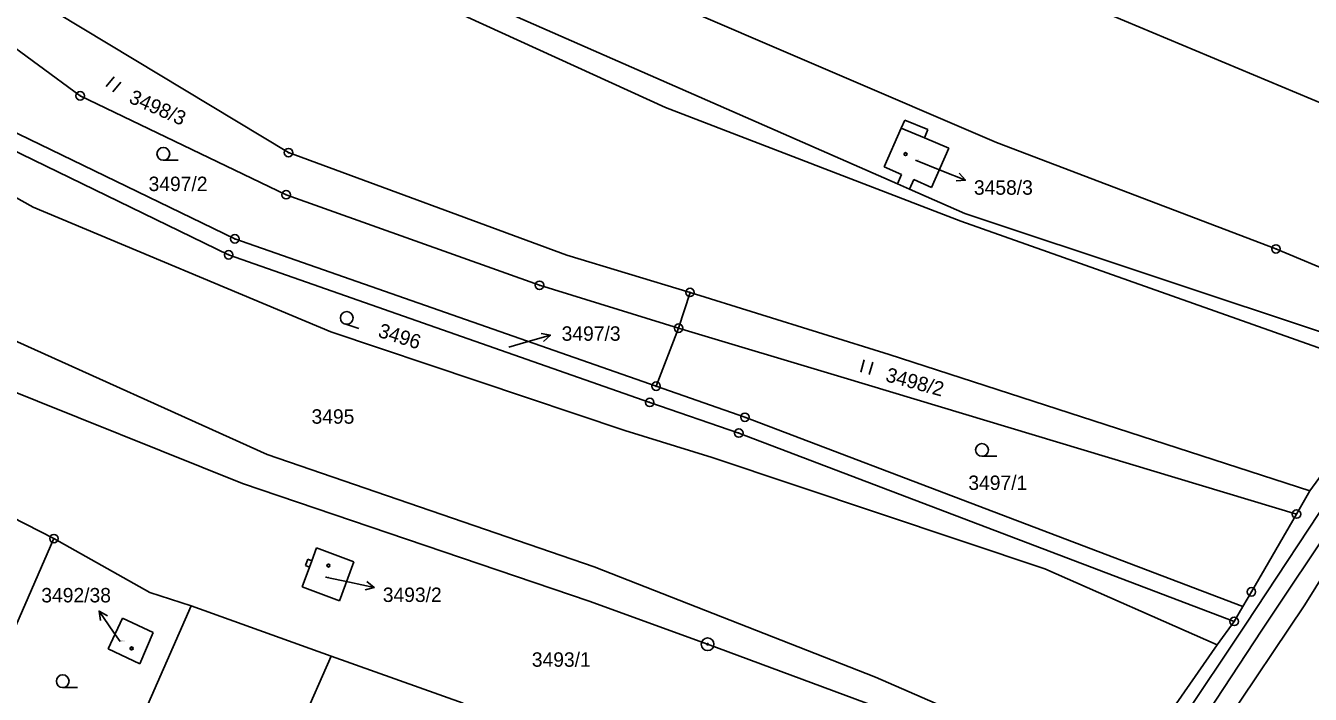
# Model space of a CAD drawing. Extents: x -593183 to -588034, y -1130415 to -1124994.
# Drawn here: x -592719.7 to -592568.1, y -1128992.3 to -1128913.5 of the extents above; entities that cross this region are included whole.
import ezdxf

# ---------------------------------------------------------------- set-up
doc = ezdxf.new("R2010")
doc.units = 0
for name, color, linetype in [('Vrstva 1', 7, 'Continuous'), ('Vrstva 16', 7, 'Continuous'), ('Vrstva 18', 7, 'Continuous'), ('Vrstva 19', 7, 'Continuous'), ('Vrstva 24', 7, 'Continuous'), ('Vrstva 25', 7, 'Continuous'), ('Vrstva 4', 7, 'Continuous')]:
    doc.layers.add(name, color=color, linetype=linetype)

msp = doc.modelspace()

# ---------------------------------------------------------------- linework, layer by layer
at = {"layer": 'Vrstva 1'}
for p, q in [((-592725.08, -1128906.53), (-592688.72, -1128928.45)), ((-592560.34, -1128925.33), (-592604.29, -1128906.93)), ((-592730.37, -1128909.25), (-592713.31, -1128921.75)), ((-592670.45, -1128908.62), (-592616.85, -1128932.14)), ((-592647.34, -1128909.17), (-592605.18, -1128927.27)), ((-592672.07, -1128910.38), (-592644.24, -1128923.12)), ((-592746.46, -1128919.64), (-592718.85, -1128934.87)), ((-592713.31, -1128921.75), (-592689.01, -1128933.41)), ((-592644.24, -1128923.12), (-592609.38, -1128936.54)), ((-592724.11, -1128924.55), (-592695.06, -1128938.62)), ((-592616.4, -1128925.56), (-592618.41, -1128930.12)), ((-592616.4, -1128925.56), (-592615.98, -1128924.6)), ((-592615.98, -1128924.6), (-592613.29, -1128925.72)), ((-592613.29, -1128925.72), (-592613.67, -1128926.7)), ((-592724.83, -1128926.41), (-592695.79, -1128940.49)), ((-592613.67, -1128926.7), (-592610.79, -1128927.92)), ((-592605.18, -1128927.27), (-592572.18, -1128939.8)), ((-592688.72, -1128928.45), (-592655.88, -1128940.52)), ((-592610.79, -1128927.92), (-592612.83, -1128932.54)), ((-592618.41, -1128930.12), (-592616.36, -1128931.02)), ((-592616.36, -1128931.02), (-592616.85, -1128932.14)), ((-592615.44, -1128932.76), (-592614.93, -1128931.61)), ((-592612.83, -1128932.54), (-592614.93, -1128931.61)), ((-592689.01, -1128933.41), (-592659.11, -1128944.09)), ((-592616.85, -1128932.14), (-592615.44, -1128932.76)), ((-592615.44, -1128932.76), (-592608.89, -1128935.63)), ((-592718.85, -1128934.87), (-592683.72, -1128949.59)), ((-592609.38, -1128936.54), (-592561.5, -1128953.47)), ((-592608.89, -1128935.63), (-592556.96, -1128952.9)), ((-592695.06, -1128938.62), (-592645.35, -1128955.99)), ((-592695.79, -1128940.49), (-592646.09, -1128957.9)), ((-592655.88, -1128940.52), (-592641.34, -1128944.93)), ((-592572.18, -1128939.8), (-592552.97, -1128947.89)), ((-592659.11, -1128944.09), (-592642.68, -1128949.14)), ((-592641.34, -1128944.93), (-592642.68, -1128949.14)), ((-592641.34, -1128944.93), (-592617.85, -1128952.25)), ((-592723.17, -1128949.66), (-592691.23, -1128964.05)), ((-592683.72, -1128949.59), (-592649.03, -1128961.22)), ((-592642.68, -1128949.14), (-592645.35, -1128955.99)), ((-592642.68, -1128949.14), (-592623.16, -1128954.99)), ((-592617.85, -1128952.25), (-592568.19, -1128968.32)), ((-592726.03, -1128954.69), (-592694.14, -1128967.46)), ((-592568.19, -1128968.32), (-592558.14, -1128954.51)), ((-592645.35, -1128955.99), (-592634.86, -1128959.65)), ((-592623.16, -1128954.99), (-592569.76, -1128971.06)), ((-592646.09, -1128957.9), (-592635.58, -1128961.51)), ((-592634.86, -1128959.65), (-592576.1, -1128981.97)), ((-592649.03, -1128961.22), (-592638.73, -1128964.38)), ((-592635.58, -1128961.51), (-592577.11, -1128983.72)), ((-592691.23, -1128964.05), (-592652.67, -1128977.29)), ((-592638.73, -1128964.38), (-592599.47, -1128977.54)), ((-592558.48, -1128965.23), (-592568.79, -1128981.77)), ((-592727.81, -1128968.16), (-592716.41, -1128973.96)), ((-592694.14, -1128967.46), (-592653.24, -1128981.33)), ((-592568.19, -1128968.32), (-592569.76, -1128971.06)), ((-592575.08, -1128980.23), (-592569.76, -1128971.06)), ((-592716.41, -1128973.96), (-592725.11, -1128993.8)), ((-592716.41, -1128973.96), (-592705.1, -1128980.31)), ((-592685.99, -1128976.56), (-592685.43, -1128975.05)), ((-592685.43, -1128975.05), (-592681.01, -1128976.68)), ((-592687.13, -1128979.66), (-592686.26, -1128977.31)), ((-592686.73, -1128977.13), (-592686.46, -1128976.38)), ((-592686.26, -1128977.31), (-592686.73, -1128977.13)), ((-592686.46, -1128976.38), (-592685.99, -1128976.56)), ((-592681.01, -1128976.68), (-592682.71, -1128981.29)), ((-592652.67, -1128977.29), (-592619.43, -1128990.29)), ((-592599.47, -1128977.54), (-592579.11, -1128986.5)), ((-592705.1, -1128980.31), (-592700.22, -1128981.88)), ((-592682.71, -1128981.29), (-592687.13, -1128979.66)), ((-592576.1, -1128981.97), (-592575.08, -1128980.23)), ((-592700.22, -1128981.88), (-592708.62, -1129001.03)), ((-592700.22, -1128981.88), (-592683.7, -1128987.81)), ((-592653.24, -1128981.33), (-592639.27, -1128986.41)), ((-592568.79, -1128981.77), (-592584.04, -1129004.42)), ((-592577.11, -1128983.72), (-592576.1, -1128981.97)), ((-592710, -1128986.97), (-592708.31, -1128983.35)), ((-592708.31, -1128983.35), (-592704.68, -1128985.04)), ((-592704.68, -1128985.04), (-592706.28, -1128988.71)), ((-592579.11, -1128986.5), (-592577.11, -1128983.72)), ((-592639.27, -1128986.41), (-592619.45, -1128993.77)), ((-592579.11, -1128986.5), (-592590.56, -1129002.83)), ((-592706.28, -1128988.71), (-592710, -1128986.97)), ((-592683.7, -1128987.81), (-592692.58, -1129008.06)), ((-592683.7, -1128987.81), (-592668.12, -1128993.38)), ((-592590.56, -1129002.83), (-592619.43, -1128990.29))]:
    msp.add_line(p, q, dxfattribs=at)
at = {"layer": 'Vrstva 16'}
for p, q in [((-592614.73, -1128929.32), (-592611.61, -1128930.58)), ((-592662.74, -1128951.37), (-592660.7, -1128950.79)), ((-592684.37, -1128978.5), (-592681.53, -1128979.1)), ((-592708.61, -1128986.08), (-592709.37, -1128984.98))]:
    msp.add_line(p, q, dxfattribs=at)
at = {"layer": 'Vrstva 24'}
for centre, radius in [((-592713.31, -1128921.75), 0.5), ((-592713.31, -1128921.75), 0.0327), ((-592688.72, -1128928.45), 0.5), ((-592688.72, -1128928.45), 0.0327), ((-592689.01, -1128933.41), 0.5), ((-592689.01, -1128933.41), 0.0327), ((-592695.06, -1128938.62), 0.5), ((-592695.06, -1128938.62), 0.0327), ((-592572.18, -1128939.8), 0.5), ((-592695.79, -1128940.49), 0.5), ((-592695.79, -1128940.49), 0.0327), ((-592572.18, -1128939.8), 0.0327), ((-592659.11, -1128944.09), 0.5), ((-592659.11, -1128944.09), 0.0327), ((-592641.34, -1128944.93), 0.5), ((-592641.34, -1128944.93), 0.0327), ((-592642.68, -1128949.14), 0.5), ((-592642.68, -1128949.14), 0.0327), ((-592645.35, -1128955.99), 0.5), ((-592645.35, -1128955.99), 0.0327), ((-592646.09, -1128957.9), 0.5), ((-592646.09, -1128957.9), 0.0327), ((-592634.86, -1128959.65), 0.5), ((-592634.86, -1128959.65), 0.0327), ((-592635.58, -1128961.51), 0.5), ((-592635.58, -1128961.51), 0.0327), ((-592569.76, -1128971.06), 0.5), ((-592569.76, -1128971.06), 0.0327), ((-592716.41, -1128973.96), 0.5), ((-592716.41, -1128973.96), 0.0327), ((-592575.08, -1128980.23), 0.5), ((-592575.08, -1128980.23), 0.0327), ((-592577.11, -1128983.72), 0.5), ((-592577.11, -1128983.72), 0.0327), ((-592639.27, -1128986.41), 0.75), ((-592639.27, -1128986.41), 0.0903)]:
    msp.add_circle(centre, radius, dxfattribs=at)
at = {"layer": 'Vrstva 25'}
for p, q in [((-592709.29, -1128919.49), (-592710.23, -1128920.65)), ((-592709.44, -1128921.29), (-592708.5, -1128920.13)), ((-592701.75, -1128929.34), (-592703.5, -1128929.34)), ((-592611.61, -1128930.58), (-592608.83, -1128931.71)), ((-592680.42, -1128949.18), (-592682.08, -1128948.64)), ((-592660.7, -1128950.79), (-592657.81, -1128949.97)), ((-592620.77, -1128952.89), (-592621.17, -1128954.34)), ((-592620.18, -1128954.61), (-592619.78, -1128953.16)), ((-592605.13, -1128964.25), (-592606.88, -1128964.25)), ((-592681.53, -1128979.1), (-592678.6, -1128979.73)), ((-592709.37, -1128984.98), (-592711.08, -1128982.51)), ((-592713.62, -1128991.52), (-592715.37, -1128991.52))]:
    msp.add_line(p, q, dxfattribs=at)
for points in [[(-592609.57, -1128930.87), (-592608.83, -1128931.71), (-592609.94, -1128931.79)], [(-592658.91, -1128949.76), (-592657.81, -1128949.97), (-592658.64, -1128950.72)], [(-592679.47, -1128979.03), (-592678.6, -1128979.73), (-592679.68, -1128980.01)], [(-592710.92, -1128983.62), (-592711.08, -1128982.51), (-592710.1, -1128983.05)]]:
    msp.add_lwpolyline(points, dxfattribs=at)
for centre, radius in [((-592703.5, -1128928.59), 0.75), ((-592615.9, -1128928.62), 0.175), ((-592615.9, -1128928.62), 0.15), ((-592681.85, -1128947.93), 0.75), ((-592606.88, -1128963.5), 0.75), ((-592684.01, -1128977.14), 0.175), ((-592684.01, -1128977.14), 0.15), ((-592707.24, -1128986.91), 0.175), ((-592707.24, -1128986.91), 0.15), ((-592715.37, -1128990.77), 0.75)]:
    msp.add_circle(centre, radius, dxfattribs=at)
at = {"layer": 'Vrstva 4'}
for p, q in [((-592616.4, -1128925.56), (-592613.67, -1128926.7)), ((-592555.37, -1128953.14), (-592575.74, -1128984.03)), ((-592552.99, -1128953.49), (-592573.87, -1128984.74)), ((-592686.26, -1128977.31), (-592685.99, -1128976.56)), ((-592575.74, -1128984.03), (-592588.62, -1129003.3)), ((-592573.87, -1128984.74), (-592586.38, -1129003.85))]:
    msp.add_line(p, q, dxfattribs=at)

# ---------------------------------------------------------------- texts
at = {"layer": 'Vrstva 16'}
for s, p in [('3458/3', (-592607.83, -1128933.41)), ('3497/3', (-592656.49, -1128950.63)), ('3492/38', (-592717.9, -1128981.48)), ('3493/2', (-592677.6, -1128981.43))]:
    msp.add_text(s, height=1.7, dxfattribs=at).set_placement(p)
at = {"layer": 'Vrstva 18'}
for s, rotation, p in [('3498/3', 336.342, (-592707.68, -1128922.51)), ('3496', 342.4908, (-592678.26, -1128950.14)), ('3498/2', 344.6719, (-592618.36, -1128955.38))]:
    msp.add_text(s, height=1.7, rotation=rotation, dxfattribs=at).set_placement(p)
for s, height, p in [('3497/2', 1.7, (-592705.24, -1128932.98)), ('3497/3', 0.1, (-592662.74, -1128951.37)), ('3495', 1.7, (-592686.01, -1128960.41)), ('3497/1', 1.7, (-592608.49, -1128968.22)), ('3493/1', 1.7, (-592660.01, -1128989.07))]:
    msp.add_text(s, height=height, dxfattribs=at).set_placement(p)
at = {"layer": 'Vrstva 19'}
for s, p in [('3458/3', (-592614.73, -1128929.32)), ('3493/2', (-592684.37, -1128978.5)), ('3492/38', (-592708.61, -1128986.08))]:
    msp.add_text(s, height=0.1, dxfattribs=at).set_placement(p)

doc.saveas('drawing.dxf')
